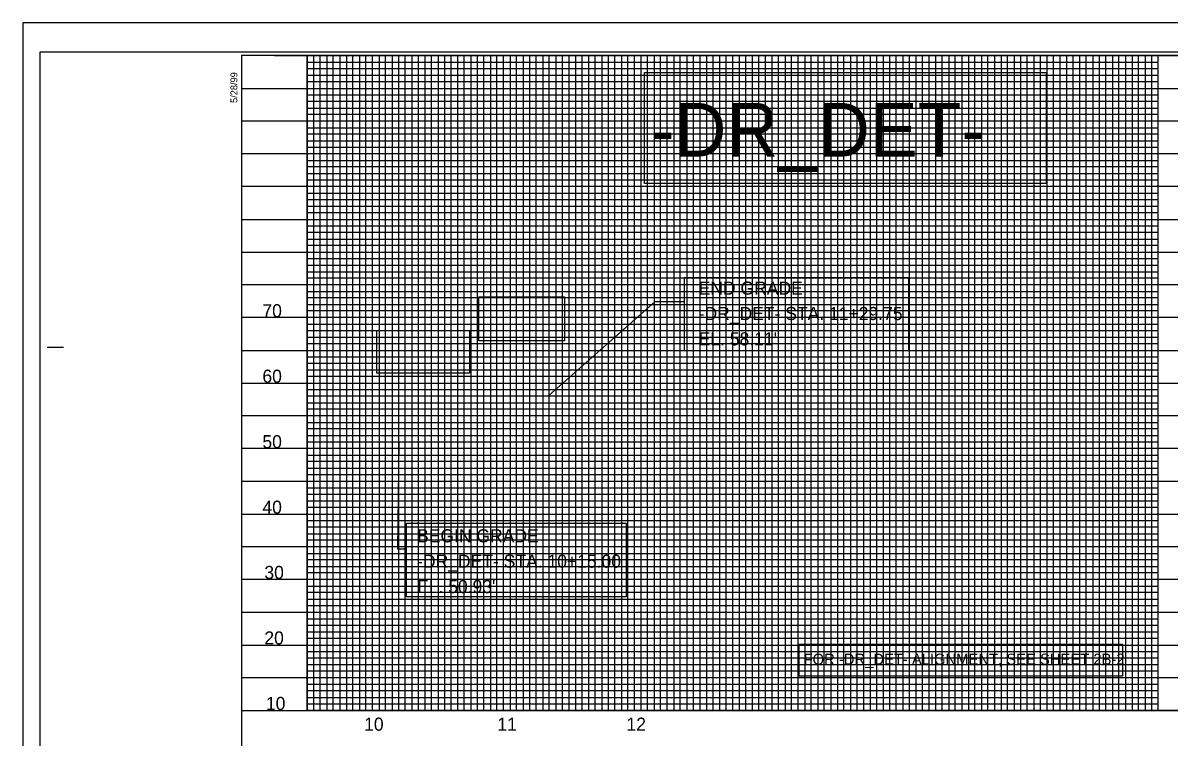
# Model space of a CAD drawing. Extents: x 1019474 to 1021158, y 503201 to 504732.
# Drawn here: x 1019474 to 1020350, y 503755 to 504301 of the extents above; entities that cross this region are included whole.
import ezdxf

# ---------------------------------------------------------------- set-up
doc = ezdxf.new("R2010")
doc.units = 0
for name, color, linetype in [('Exist Vertical Profile Horizontal Axis Label Major', 7, 'Continuous'), ('Exist Vertical Profile Vertical Axis Label', 7, 'Continuous'), ('Prop Grid Mask', 7, 'Continuous'), ('Prop Horizontal Alignment Station Label', 7, 'Continuous'), ('Prop Vertical Profile Grade Label', 7, 'Continuous'), ('Prop VPI Label', 7, 'Continuous'), ('Scratch_Level_0', 7, 'Continuous'), ('Sheet Cutting Line CELL', 7, 'Continuous'), ('Sheet Layout Profile Border Port 1', 7, 'Continuous'), ('Sheet Layout Profile Border Port 2', 7, 'Continuous'), ('Sheet Plot Border Inside CELL', 7, 'Continuous'), ('Sheet Plot Border Outside CELL', 7, 'Continuous'), ('Sheet Profile CELL', 7, 'Continuous'), ('Sheet Profile Grid Major CELL', 7, 'Continuous'), ('Sheet Profile Grid Middle CELL', 7, 'Continuous'), ('Sheet Profile Grid Minor CELL', 7, 'Continuous')]:
    doc.layers.add(name, color=color, linetype=linetype)

msp = doc.modelspace()

# ---------------------------------------------------------------- linework, layer by layer
at = {"layer": 'Prop Grid Mask'}
for points in [[(1019948.92, 504262.93), (1020255.56, 504262.93), (1020255.56, 504178.16), (1019948.92, 504178.16)], [(1019979.37, 504106.38), (1020150.47, 504106.38), (1020150.47, 504050.22), (1019979.37, 504050.22)], [(1019822.3, 504091.53), (1019887.74, 504091.53), (1019887.74, 504057.9), (1019822.3, 504057.9)], [(1019744.37, 504065.82), (1019815.34, 504065.82), (1019815.34, 504033.35), (1019744.37, 504033.35)], [(1019767.03, 503918.86), (1019934.87, 503918.86), (1019934.87, 503862.54), (1019767.03, 503862.54)], [(1020067.02, 503826.39), (1020314.03, 503826.39), (1020314.03, 503802), (1020067.02, 503802)]]:
    msp.add_lwpolyline(points, close=True, dxfattribs=at)
at = {"layer": 'Prop Vertical Profile Grade Label'}
for p, q in [((1019875.97, 504016.25), (1019956.78, 504087.74)), ((1019979.83, 504087.74), (1019956.78, 504087.74)), ((1019761.22, 503980.34), (1019760.21, 503898.88)), ((1019767.12, 503898.88), (1019760.21, 503898.88))]:
    msp.add_line(p, q, dxfattribs=at)
at = {"layer": 'Scratch_Level_0'}
msp.add_lwpolyline([(1019691.22, 503775.7), (1019691.22, 504275.7), (1020941.22, 504275.7), (1020941.17, 504114.65), (1021091.22, 504114.65), (1021091.22, 503775.7)], close=True, dxfattribs=at)
at = {"layer": 'Sheet Cutting Line CELL'}
for p, q in [((1021158.22, 504300.7), (1019474.22, 504300.7)), ((1019474.22, 504300.7), (1019474.22, 503200.7))]:
    msp.add_line(p, q, dxfattribs=at)
at = {"layer": 'Sheet Layout Profile Border Port 1'}
msp.add_lwpolyline([(1019691.22, 504114.65), (1019691.22, 503775.7), (1021091.22, 503775.7), (1021091.22, 504114.65)], dxfattribs=at)
at = {"layer": 'Sheet Layout Profile Border Port 2'}
msp.add_lwpolyline([(1019691.22, 504275.7), (1020941.22, 504275.7), (1020941.17, 504114.65), (1021091.22, 504114.65), (1021091.22, 503775.7), (1019691.22, 503775.7)], close=True, dxfattribs=at)
at = {"layer": 'Sheet Plot Border Inside CELL'}
msp.add_lwpolyline([(1019487.22, 503223.15), (1021153.72, 503223.15), (1021153.72, 504278.25), (1019487.22, 504278.25)], close=True, dxfattribs=at)
at = {"layer": 'Sheet Plot Border Outside CELL'}
msp.add_lwpolyline([(1019474.22, 503200.7), (1021158.22, 503200.7), (1021158.22, 504300.7), (1019474.22, 504300.7)], close=True, dxfattribs=at)
at = {"layer": 'Sheet Profile CELL'}
for p, q in [((1019492.72, 504053.2), (1019505.22, 504053.2)), ((1019641.22, 503775.7), (1021141.22, 503775.7))]:
    msp.add_line(p, q, dxfattribs=at)
msp.add_lwpolyline([(1021141.22, 504275.7), (1019641.22, 504275.7), (1019641.22, 503225.7), (1021141.22, 503225.7)], close=True, dxfattribs=at)
at = {"layer": 'Sheet Profile Grid Major CELL'}
for p, q in [((1019691.22, 504275.7), (1019691.22, 503775.7)), ((1019741.22, 503775.7), (1019741.22, 504275.7)), ((1019741.22, 504275.7), (1019791.22, 504275.7)), ((1019791.22, 504275.7), (1019791.22, 503775.7)), ((1019841.22, 503775.7), (1019841.22, 504275.7)), ((1019841.22, 504275.7), (1019891.22, 504275.7)), ((1019891.22, 504275.7), (1019891.22, 503775.7)), ((1019941.22, 503775.7), (1019941.22, 504275.7)), ((1019941.22, 504275.7), (1019991.22, 504275.7)), ((1019991.22, 504275.7), (1019991.22, 503775.7)), ((1020041.22, 503775.7), (1020041.22, 504275.7)), ((1020041.22, 504275.7), (1020091.22, 504275.7)), ((1020091.22, 504275.7), (1020091.22, 503775.7)), ((1020141.22, 503775.7), (1020141.22, 504275.7)), ((1020141.22, 504275.7), (1020191.22, 504275.7)), ((1020191.22, 504275.7), (1020191.22, 503775.7)), ((1020241.22, 503775.7), (1020241.22, 504275.7)), ((1020241.22, 504275.7), (1020291.22, 504275.7)), ((1020291.22, 504275.7), (1020291.22, 503775.7)), ((1020341.22, 503775.7), (1020341.22, 504275.7)), ((1020341.22, 504275.7), (1020391.22, 504275.7)), ((1019691.22, 503775.7), (1019741.22, 503775.7)), ((1019791.22, 503775.7), (1019841.22, 503775.7)), ((1019891.22, 503775.7), (1019941.22, 503775.7)), ((1019991.22, 503775.7), (1020041.22, 503775.7)), ((1020091.22, 503775.7), (1020141.22, 503775.7)), ((1020191.22, 503775.7), (1020241.22, 503775.7)), ((1020291.22, 503775.7), (1020341.22, 503775.7))]:
    msp.add_line(p, q, dxfattribs=at)
for points in [[(1020941.17, 504225.7), (1019641.22, 504225.7)], [(1020941.17, 504175.7), (1019641.22, 504175.7), (1019641.22, 504125.7), (1020941.17, 504125.7)], [(1021141.22, 504075.7), (1019641.22, 504075.7), (1019641.22, 504025.7), (1021141.22, 504025.7)], [(1021141.22, 503975.7), (1019641.22, 503975.7), (1019641.22, 503925.7), (1021141.22, 503925.7)], [(1021141.22, 503875.7), (1019641.22, 503875.7), (1019641.22, 503875.7), (1019641.22, 503825.7), (1021141.22, 503825.7)]]:
    msp.add_lwpolyline(points, dxfattribs=at)
at = {"layer": 'Sheet Profile Grid Middle CELL'}
for points in [[(1019666.22, 504275.7), (1019716.22, 504275.7), (1019716.22, 503775.7), (1019766.22, 503775.7), (1019766.22, 504275.7), (1019816.22, 504275.7), (1019816.22, 503775.7), (1019866.22, 503775.7), (1019866.22, 504275.7), (1019916.22, 504275.7), (1019916.22, 503775.7), (1019966.22, 503775.7), (1019966.22, 504275.7), (1020016.22, 504275.7), (1020016.22, 503775.7), (1020066.22, 503775.7), (1020066.22, 504275.7), (1020116.22, 504275.7), (1020116.22, 503775.7), (1020166.22, 503775.7), (1020166.22, 504275.7), (1020216.22, 504275.7), (1020216.22, 503775.7), (1020266.22, 503775.7), (1020266.22, 503775.7), (1020266.22, 504275.7), (1020316.22, 504275.7), (1020316.22, 503775.7), (1020341.22, 503775.7)], [(1019641.22, 504250.7), (1020941.22, 504250.7)], [(1020941.17, 504200.7), (1019641.22, 504200.7), (1019641.22, 504150.7), (1020941.17, 504150.7)], [(1021141.22, 504100.7), (1019641.22, 504100.7), (1019641.22, 504050.7), (1021141.22, 504050.7)], [(1021141.22, 504000.7), (1019641.22, 504000.7), (1019641.22, 503950.7), (1021141.22, 503950.7)], [(1021141.22, 503900.7), (1019641.22, 503900.7), (1019641.22, 503850.7), (1021141.22, 503850.7)], [(1021141.22, 503800.7), (1019641.22, 503800.7)]]:
    msp.add_lwpolyline(points, dxfattribs=at)
at = {"layer": 'Sheet Profile Grid Minor CELL'}
for p, q in [((1019691.22, 504270.7), (1020341.22, 504270.7)), ((1019691.22, 504265.7), (1019691.22, 504265.7)), ((1020341.22, 504265.7), (1019691.22, 504265.7)), ((1019691.22, 504260.7), (1020341.22, 504260.7)), ((1020341.22, 504255.7), (1019691.22, 504255.7)), ((1019691.22, 504245.7), (1020341.22, 504245.7)), ((1020341.22, 504240.7), (1019691.22, 504240.7)), ((1019691.22, 504235.7), (1020341.22, 504235.7)), ((1020341.22, 504230.7), (1019691.22, 504230.7)), ((1019691.22, 504220.7), (1020341.22, 504220.7)), ((1020341.22, 504215.7), (1019691.22, 504215.7)), ((1019691.22, 504210.7), (1020341.22, 504210.7)), ((1020341.22, 504205.7), (1019691.22, 504205.7)), ((1019691.22, 504195.7), (1020341.22, 504195.7)), ((1020341.22, 504190.7), (1019691.22, 504190.7)), ((1019691.22, 504185.7), (1020341.22, 504185.7)), ((1020341.22, 504180.7), (1019691.22, 504180.7)), ((1019691.22, 504170.7), (1020341.22, 504170.7)), ((1020341.22, 504165.7), (1019691.22, 504165.7)), ((1019691.22, 504160.7), (1020341.22, 504160.7)), ((1020341.22, 504155.7), (1019691.22, 504155.7)), ((1019691.22, 504145.7), (1020341.22, 504145.7)), ((1020341.22, 504140.7), (1019691.22, 504140.7)), ((1019691.22, 504135.7), (1020341.22, 504135.7)), ((1020341.22, 504130.7), (1019691.22, 504130.7)), ((1019691.22, 504120.7), (1020341.22, 504120.7)), ((1019691.22, 504115.7), (1020341.22, 504115.7)), ((1019691.22, 504110.7), (1020341.22, 504110.7)), ((1020341.22, 504105.7), (1019691.22, 504105.7)), ((1019691.22, 504095.7), (1020341.22, 504095.7)), ((1020341.22, 504090.7), (1019691.22, 504090.7)), ((1019691.22, 504085.7), (1020341.22, 504085.7)), ((1020341.22, 504080.78), (1019691.22, 504080.85)), ((1019691.22, 504070.7), (1020341.22, 504070.7)), ((1020341.22, 504065.7), (1019691.22, 504065.7)), ((1019691.22, 504060.7), (1020341.22, 504060.7)), ((1020341.22, 504055.7), (1019691.22, 504055.7)), ((1019691.22, 504045.7), (1020341.22, 504045.7)), ((1020341.22, 504040.7), (1019691.22, 504040.7)), ((1019691.22, 504035.7), (1020341.22, 504035.7)), ((1020341.22, 504030.7), (1019691.22, 504030.7)), ((1019691.22, 504020.7), (1020341.22, 504020.7)), ((1020341.22, 504015.7), (1019691.22, 504015.7)), ((1019691.22, 504010.7), (1020341.22, 504010.7)), ((1020341.22, 504005.7), (1019691.22, 504005.7)), ((1019691.22, 503995.7), (1020341.22, 503995.7)), ((1020341.22, 503990.7), (1019691.22, 503990.7)), ((1019691.22, 503985.7), (1020341.22, 503985.7)), ((1020341.22, 503980.7), (1019691.22, 503980.7)), ((1019691.22, 503970.7), (1020341.22, 503970.7)), ((1020341.22, 503965.7), (1019691.22, 503965.7)), ((1019691.22, 503960.7), (1020341.22, 503960.7)), ((1020341.22, 503955.7), (1019691.22, 503955.7)), ((1019691.22, 503945.7), (1020341.22, 503945.7)), ((1020341.22, 503940.7), (1019691.22, 503940.7)), ((1019691.22, 503935.7), (1020341.22, 503935.7)), ((1020341.22, 503930.7), (1019691.22, 503930.7)), ((1019691.22, 503920.7), (1020341.22, 503920.7)), ((1020341.22, 503915.7), (1019691.22, 503915.7)), ((1019691.22, 503910.7), (1020341.22, 503910.7)), ((1020341.22, 503905.7), (1019691.22, 503905.7)), ((1019691.22, 503895.7), (1020341.22, 503895.7)), ((1020341.22, 503890.7), (1019691.22, 503890.7)), ((1019691.22, 503885.7), (1020341.22, 503885.7)), ((1020341.22, 503880.7), (1019691.22, 503880.7)), ((1019691.22, 503870.7), (1020341.22, 503870.7)), ((1020341.22, 503865.7), (1019691.22, 503865.7)), ((1019691.22, 503860.7), (1020341.22, 503860.7)), ((1020341.22, 503855.7), (1019691.22, 503855.7)), ((1019691.22, 503845.7), (1020341.22, 503845.7)), ((1020341.22, 503840.7), (1019691.22, 503840.7)), ((1019691.22, 503835.7), (1020341.22, 503835.7)), ((1020341.22, 503830.7), (1019691.22, 503830.7)), ((1019691.22, 503820.7), (1020341.22, 503820.7)), ((1020341.22, 503815.7), (1019691.22, 503815.7)), ((1019691.22, 503810.7), (1020341.22, 503810.7)), ((1020341.22, 503805.7), (1019691.22, 503805.7)), ((1019691.22, 503795.7), (1020341.22, 503795.7)), ((1020341.22, 503790.7), (1019691.22, 503790.7)), ((1019691.22, 503785.7), (1020341.22, 503785.7)), ((1019691.22, 503780.7), (1020341.22, 503780.7))]:
    msp.add_line(p, q, dxfattribs=at)
for points in [[(1019691.22, 504275.7), (1019696.22, 504275.7), (1019696.22, 503775.7), (1019701.22, 503775.7), (1019701.22, 504275.7), (1019706.22, 504275.7), (1019706.22, 503775.7), (1019711.22, 503775.7), (1019711.22, 504275.7), (1019721.22, 504275.7), (1019721.22, 503775.7), (1019726.22, 503775.7), (1019726.22, 504275.7), (1019731.22, 504275.7), (1019731.22, 503775.7), (1019736.22, 503775.7), (1019746.22, 503775.7), (1019751.22, 503775.7), (1019751.22, 504275.7), (1019756.22, 504275.7), (1019756.22, 503775.7), (1019761.22, 503775.7), (1019761.22, 504275.7), (1019771.22, 504275.7), (1019771.22, 503775.7), (1019776.22, 503775.7), (1019776.22, 504275.7), (1019781.22, 504275.7), (1019781.22, 503775.7), (1019786.22, 503775.7), (1019786.22, 504275.7), (1019796.22, 504275.7), (1019796.22, 503775.7), (1019801.22, 503775.7), (1019801.22, 504275.7), (1019806.22, 504275.7), (1019806.22, 503775.7), (1019811.22, 503775.7), (1019811.22, 504275.7), (1019821.22, 504275.7), (1019821.22, 503775.7), (1019826.22, 503775.7), (1019826.22, 504275.7), (1019831.22, 504275.7), (1019831.22, 503775.7), (1019836.22, 503775.7), (1019836.22, 504275.7), (1019846.22, 504275.7), (1019846.22, 503775.7), (1019851.22, 503775.7), (1019851.22, 504275.7), (1019856.22, 504275.7), (1019856.22, 503775.7), (1019861.22, 503775.7), (1019861.22, 504275.7), (1019871.22, 504275.7), (1019871.22, 503775.7), (1019876.22, 503775.7), (1019876.22, 504275.7), (1019881.22, 504275.7), (1019881.22, 503775.7), (1019886.22, 503775.7), (1019886.22, 504275.7), (1019896.22, 504275.7), (1019896.22, 503775.7), (1019901.22, 503775.7), (1019901.22, 504275.7), (1019906.22, 504275.7), (1019906.22, 503775.7)], [(1019736.22, 503775.7), (1019736.22, 504275.7), (1019746.22, 504275.7), (1019746.22, 503775.7)], [(1019906.22, 503775.7), (1019911.22, 503775.7), (1019911.22, 504275.7), (1019921.22, 504275.7), (1019921.22, 503775.7), (1019926.22, 503775.7), (1019926.22, 504275.7), (1019931.22, 504275.7), (1019931.22, 503775.7), (1019936.22, 503775.7), (1019936.22, 504275.7), (1019946.22, 504275.7), (1019946.22, 503775.7), (1019951.22, 503775.7), (1019951.22, 504275.7), (1019956.22, 504275.7), (1019956.22, 503775.7), (1019961.22, 503775.7), (1019961.22, 504275.7), (1019971.22, 504275.7), (1019971.22, 503775.7), (1019976.22, 503775.7), (1019976.22, 504275.7), (1019981.22, 504275.7), (1019981.22, 503775.7), (1019986.22, 503775.7), (1019986.22, 504275.7), (1019996.22, 504275.7), (1019996.22, 503775.7), (1020001.22, 503775.7), (1020001.22, 504275.7), (1020006.22, 504275.7), (1020006.22, 503775.7), (1020011.22, 503775.7), (1020011.22, 504275.7), (1020021.22, 504275.7), (1020021.22, 503775.7), (1020026.22, 503775.7), (1020026.22, 504275.7), (1020031.22, 504275.7), (1020031.22, 503775.7), (1020036.22, 503775.7), (1020036.22, 504275.7), (1020046.22, 504275.7), (1020046.22, 503775.7), (1020051.22, 503775.7), (1020051.22, 504275.7), (1020056.22, 504275.7), (1020056.22, 503775.7), (1020061.22, 503775.7), (1020061.22, 504275.7), (1020071.22, 504275.7), (1020071.22, 503775.7), (1020076.22, 503775.7), (1020076.22, 504275.7), (1020081.22, 504275.7), (1020081.22, 503775.7), (1020086.22, 503775.7), (1020086.22, 504275.7), (1020096.22, 504275.7), (1020096.22, 503775.7), (1020101.22, 503775.7), (1020101.22, 504275.7), (1020106.22, 504275.7), (1020106.22, 503775.7), (1020111.22, 503775.7), (1020111.22, 504275.7), (1020121.22, 504275.7), (1020121.22, 503775.7), (1020126.22, 503775.7), (1020126.22, 504275.7), (1020131.22, 504275.7), (1020131.22, 503775.7), (1020136.22, 503775.7), (1020136.22, 504275.7), (1020146.22, 504275.7), (1020146.22, 503775.7), (1020151.22, 503775.7), (1020151.22, 504275.7), (1020156.22, 504275.7), (1020156.22, 503775.7), (1020161.22, 503775.7), (1020161.22, 504275.7), (1020171.22, 504275.7), (1020171.22, 503775.7), (1020176.22, 503775.7), (1020176.22, 504275.7), (1020181.22, 504275.7), (1020181.22, 503775.7), (1020186.22, 503775.7), (1020186.22, 504275.7), (1020196.22, 504275.7), (1020196.22, 503775.7), (1020201.22, 503775.7), (1020201.22, 504275.7), (1020206.22, 504275.7), (1020206.22, 503775.7), (1020211.22, 503775.7), (1020211.22, 504275.7), (1020221.22, 504275.7)], [(1020221.22, 504275.7), (1020221.22, 503775.7), (1020226.22, 503775.7), (1020226.22, 504275.7), (1020231.22, 504275.7), (1020231.22, 503775.7), (1020236.22, 503775.7), (1020236.22, 504275.7), (1020246.22, 504275.7), (1020246.22, 503775.7), (1020251.22, 503775.7), (1020251.22, 504275.7), (1020256.22, 504275.7), (1020256.22, 503775.7), (1020261.22, 503775.7), (1020261.22, 504275.7), (1020271.22, 504275.7), (1020271.22, 503775.7), (1020276.22, 503775.7), (1020276.22, 504275.7), (1020281.22, 504275.7), (1020281.22, 503775.7), (1020286.22, 503775.7), (1020286.22, 504275.7), (1020296.22, 504275.7), (1020296.22, 503775.7), (1020301.22, 503775.7), (1020301.22, 504275.7), (1020306.22, 504275.7), (1020306.22, 503775.7), (1020311.22, 503775.7), (1020311.22, 504275.7), (1020321.22, 504275.7), (1020321.22, 503775.7), (1020326.22, 503775.7), (1020326.22, 504275.7), (1020331.22, 504275.7), (1020331.22, 503775.7), (1020336.22, 503775.7), (1020336.22, 504275.7), (1020341.22, 504275.7)]]:
    msp.add_lwpolyline(points, dxfattribs=at)

# ---------------------------------------------------------------- texts
at = {"layer": 'Exist Vertical Profile Horizontal Axis Label Major'}
for s, p in [('10', (1019734.81, 503760.26)), ('11', (1019836.57, 503760.26)), ('12', (1019935.14, 503760.26))]:
    msp.add_text(s, height=10, dxfattribs=at).set_placement(p)
at = {"layer": 'Exist Vertical Profile Vertical Axis Label'}
for s, p in [('70', (1019657.11, 504075.95)), ('60', (1019657.11, 504025.95)), ('50', (1019657.11, 503975.95)), ('40', (1019657.11, 503925.95)), ('30', (1019658.61, 503876.1)), ('20', (1019658.61, 503826.1)), ('10', (1019659.8, 503776.1))]:
    msp.add_text(s, height=10, dxfattribs=at).set_placement(p)
at = {"layer": 'Prop Horizontal Alignment Station Label'}
msp.add_text('FOR -DR_DET- ALIGNMENT, SEE SHEET 2B-2', height=8.4375, dxfattribs=at).set_placement((1020070.39, 503810.67))
at = {"layer": 'Prop Vertical Profile Grade Label'}
for s, p in [('END GRADE', (1019990.27, 504093.2)), ('-DR_DET- STA. 11+29.75', (1019990.27, 504073.82)), ("EL. 58.11'", (1019990.27, 504054.45)), ('BEGIN GRADE', (1019775.25, 503904.09)), ('-DR_DET- STA. 10+15.00', (1019775.25, 503884.72)), ("EL. 50.93'", (1019775.25, 503865.34))]:
    msp.add_text(s, height=10, rotation=360, dxfattribs=at).set_placement(p)
at = {"layer": 'Prop VPI Label'}
msp.add_text('-DR_DET-', height=40.95, dxfattribs=at).set_placement((1019953.63, 504198.68))
at = {"layer": 'Sheet Profile CELL'}
msp.add_text('5/28/99', height=5.25, rotation=90, dxfattribs=at).set_placement((1019637.98, 504239.61))

doc.saveas('drawing.dxf')
